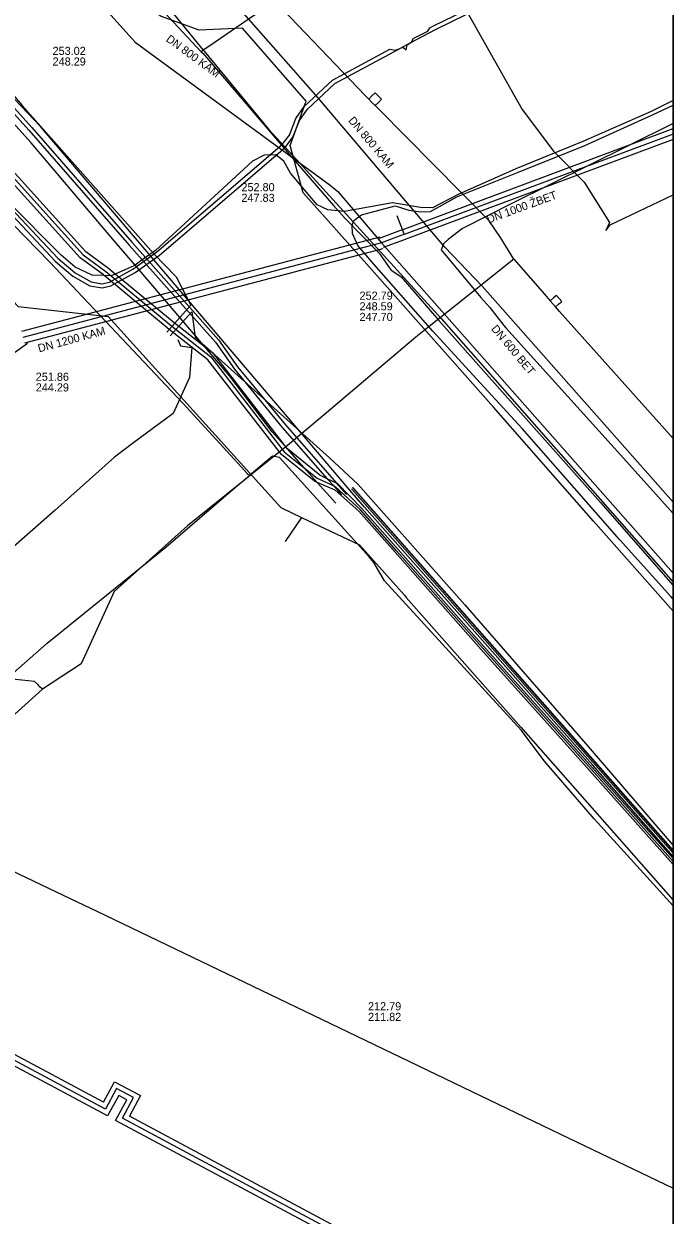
# Model space of a CAD drawing. Extents: x -598233 to -596890, y -1157848 to -1156431.
# Drawn here: x -596954.5 to -596890.5, y -1157685.2 to -1157567.6 of the extents above; entities that cross this region are included whole.
import ezdxf

# ---------------------------------------------------------------- set-up
doc = ezdxf.new("R2010")
doc.units = 0
for name, color, linetype in [('Vrstva 10', 7, 'Continuous'), ('Vrstva 12', 7, 'Continuous'), ('Vrstva 13', 7, 'Continuous'), ('Vrstva 19', 7, 'Continuous'), ('Vrstva 25', 7, 'Continuous'), ('Vrstva 26', 7, 'Continuous'), ('Vrstva 42', 7, 'Continuous'), ('Vrstva 44', 7, 'Continuous'), ('Vrstva 5', 7, 'Continuous'), ('Vrstva 55', 7, 'Continuous'), ('Vrstva 58', 7, 'Continuous'), ('Vrstva 60', 7, 'Continuous'), ('Vrstva 8', 7, 'Continuous'), ('Vrstva 9', 7, 'Continuous'), ('zajmove_uzemi', 7, 'Continuous')]:
    doc.layers.add(name, color=color, linetype=linetype)

msp = doc.modelspace()

# ---------------------------------------------------------------- linework, layer by layer
at = {"layer": 'Vrstva 10'}
for p, q in [((-596919.4, -1157588.66), (-596954.76, -1157597.98)), ((-596919.1, -1157589.82), (-596954.45, -1157599.14))]:
    msp.add_line(p, q, dxfattribs=at)
for points in [[(-596919.43, -1157588.77), (-596917.41, -1157588.01), (-596917.18, -1157587.93), (-596890.46, -1157577.95)], [(-596890.46, -1157579.02), (-596916.83, -1157588.87), (-596917.06, -1157588.95), (-596919.08, -1157589.7)], [(-596954.17, -1157599.17), (-596956.84, -1157601.09), (-596964.86, -1157604.79)]]:
    msp.add_lwpolyline(points, dxfattribs=at)
at = {"layer": 'Vrstva 12'}
for points in [[(-597004.51, -1157494.61), (-596998.59, -1157501.5), (-596997.43, -1157504.34), (-596996.05, -1157504.99), (-596988.03, -1157513.52), (-596962.05, -1157542.76), (-596956.17, -1157549.13), (-596955.06, -1157550.96), (-596953.42, -1157552.17), (-596940.63, -1157566.49), (-596937.01, -1157570.36)], [(-596908.75, -1157552.03), (-596914.18, -1157554.68), (-596933.54, -1157567.97), (-596936.17, -1157569.79), (-596936.81, -1157570.22)], [(-596940.36, -1157565.89), (-596936.81, -1157570.22)], [(-596936.81, -1157570.22), (-596937.01, -1157570.36)], [(-596937.01, -1157570.36), (-596936.87, -1157570.51), (-596927.74, -1157581.15), (-596923.96, -1157585.55)], [(-596936.81, -1157570.22), (-596936.74, -1157570.3), (-596930.39, -1157578.02), (-596927.6, -1157581.02), (-596924.03, -1157584.95)], [(-596890.46, -1157577.45), (-596894.96, -1157579.7), (-596906.38, -1157585.36), (-596911.24, -1157587.82), (-596912.65, -1157588.9)], [(-596961.18, -1157581.96), (-596959.24, -1157583.65), (-596951.95, -1157591.14), (-596938.83, -1157605.06), (-596933.05, -1157611.38)], [(-596924.03, -1157584.95), (-596921.34, -1157587.91)], [(-596923.96, -1157585.55), (-596922.82, -1157586.82)], [(-596922.82, -1157586.82), (-596919.47, -1157590.26), (-596918.3, -1157591.89), (-596917.28, -1157592.59), (-596913.58, -1157596.9), (-596897.63, -1157614.84), (-596890.46, -1157623.06)], [(-596921.34, -1157587.91), (-596913.36, -1157596.71), (-596890.46, -1157622.73)], [(-596912.65, -1157588.9), (-596913.11, -1157589.34), (-596913.34, -1157589.93), (-596909.44, -1157594.61), (-596908.55, -1157595.62), (-596907.18, -1157597.38), (-596906.96, -1157597.62)], [(-596906.96, -1157597.62), (-596895.65, -1157610.14), (-596890.46, -1157615.93)], [(-596890.46, -1157654.67), (-596898.27, -1157646.07), (-596903.2, -1157640.35), (-596905.41, -1157637.37), (-596918.95, -1157622.6), (-596919.99, -1157620.78), (-596920.44, -1157620.21), (-596929.3, -1157610.4), (-596929.99, -1157610.28), (-596932.26, -1157612.19)], [(-596933.05, -1157611.38), (-596932.49, -1157611.99), (-596932.26, -1157612.19)], [(-597014.95, -1157686.34), (-597013.23, -1157684.78), (-597010.06, -1157682.57), (-597007.42, -1157680.48), (-596999.58, -1157672.12), (-596995.14, -1157667.89), (-596981.85, -1157656.72), (-596979.91, -1157654.73), (-596976.27, -1157649.83), (-596971.68, -1157645.86), (-596965.97, -1157640.84), (-596952.21, -1157628.73), (-596940.5, -1157619.26), (-596933.64, -1157613.35), (-596932.26, -1157612.19)]]:
    msp.add_lwpolyline(points, dxfattribs=at)
at = {"layer": 'Vrstva 13'}
msp.add_line((-596927.11, -1157616.32), (-596928.74, -1157618.69), dxfattribs=at)
for points in [[(-596972.84, -1157575.03), (-596964.37, -1157585.79), (-596963.92, -1157586.27), (-596955.6, -1157594.95), (-596955.08, -1157595.5), (-596946.2, -1157596.49), (-596936.56, -1157607.15), (-596931.32, -1157612.96), (-596929.16, -1157615.35), (-596927.11, -1157616.32), (-596921.4, -1157619.04), (-596916.98, -1157624)], [(-596916.98, -1157624), (-596916.79, -1157624.23), (-596905.5, -1157637.03), (-596890.46, -1157654.09)]]:
    msp.add_lwpolyline(points, dxfattribs=at)
at = {"layer": 'Vrstva 19'}
for points in [[(-596920.49, -1157575.04), (-596920.84, -1157574.7), (-596932.64, -1157562.31)], [(-596920.18, -1157575.36), (-596920.49, -1157575.04), (-596920.18, -1157574.73)], [(-596919.86, -1157575.68), (-596919.54, -1157575.37), (-596919.22, -1157575.05), (-596919.85, -1157574.41), (-596920.18, -1157574.73)], [(-596919.86, -1157575.68), (-596920.18, -1157575.36)], [(-596906.17, -1157590.85), (-596907.5, -1157588.7), (-596908.6, -1157587.05), (-596919.54, -1157576.01), (-596919.86, -1157575.68)], [(-596906.17, -1157590.85), (-596911.85, -1157595.35)], [(-596906.17, -1157590.85), (-596903.4, -1157594.02), (-596902.59, -1157594.94), (-596902.33, -1157595.24)], [(-596902.33, -1157595.24), (-596902.07, -1157595.54), (-596901.76, -1157595.27), (-596901.45, -1157595.01), (-596901.98, -1157594.41), (-596902.28, -1157594.67), (-596902.59, -1157594.94)], [(-596911.85, -1157595.35), (-596914.36, -1157597.35), (-596915.85, -1157598.53), (-596925.09, -1157606.35), (-596928.51, -1157609.24), (-596938.36, -1157617.16), (-596945.59, -1157623.64), (-596948.86, -1157630.76), (-596952.68, -1157633.28)], [(-596890.46, -1157608.53), (-596901.66, -1157596), (-596902.07, -1157595.54)], [(-596953.15, -1157632.81), (-596953.45, -1157632.51), (-596956.6, -1157632.2), (-596957.02, -1157631.64), (-596964.22, -1157623.24), (-596965.08, -1157622.33), (-596972.86, -1157620.21), (-596973.81, -1157619.16), (-596985.37, -1157605.64), (-596986.1, -1157604.86), (-596988.52, -1157604.8)], [(-596952.68, -1157633.28), (-596952.89, -1157633.08), (-596953.15, -1157632.81)], [(-596952.68, -1157633.28), (-596971.44, -1157650.21), (-596981.79, -1157656.71), (-597002.57, -1157676.74), (-597002.84, -1157676.87), (-597001.55, -1157678.38), (-597001.29, -1157678.68)]]:
    msp.add_lwpolyline(points, dxfattribs=at)
at = {"layer": 'Vrstva 25'}
msp.add_line((-596902.32, -1157698.35), (-596944.78, -1157675.62), dxfattribs=at)
for points in [[(-596946.45, -1157674.72), (-596973.84, -1157660.06), (-596969.13, -1157651.32), (-596978.47, -1157646.29), (-597001.52, -1157643.75)], [(-596944.78, -1157675.62), (-596943.69, -1157673.59), (-596945.37, -1157672.7), (-596946.45, -1157674.72)]]:
    msp.add_lwpolyline(points, dxfattribs=at)
at = {"layer": 'Vrstva 26'}
for p, q in [((-596903.17, -1157698.46), (-596945.46, -1157675.83)), ((-596901.46, -1157698.24), (-596944.1, -1157675.42))]:
    msp.add_line(p, q, dxfattribs=at)
for points in [[(-596946.66, -1157674.05), (-596973.16, -1157659.86), (-596968.46, -1157651.11), (-596978.32, -1157645.81), (-597000.9, -1157643.31)], [(-596946.25, -1157675.4), (-596974.52, -1157660.27), (-596969.81, -1157651.52), (-596978.62, -1157646.78), (-597002.14, -1157644.18)], [(-596946.66, -1157674.05), (-596945.57, -1157672.02), (-596943.02, -1157673.39), (-596944.1, -1157675.42)], [(-596945.46, -1157675.83), (-596944.37, -1157673.8), (-596945.16, -1157673.37), (-596946.25, -1157675.4)]]:
    msp.add_lwpolyline(points, dxfattribs=at)
at = {"layer": 'Vrstva 42'}
for points in [[(-596916.12, -1157569.07), (-596914.66, -1157568.32), (-596914.46, -1157568.01), (-596914.1, -1157567.82), (-596904.93, -1157563.32), (-596900.35, -1157561.24), (-596896.86, -1157559.72), (-596890.46, -1157556.55)], [(-596956.56, -1157585.55), (-596951.43, -1157591.02), (-596949.69, -1157592.51), (-596948.01, -1157593.46), (-596946.8, -1157593.68), (-596945.92, -1157593.48), (-596943.55, -1157592.15), (-596941.14, -1157590.44), (-596928.74, -1157579.81), (-596927.97, -1157578.79), (-596927.32, -1157577.15), (-596926.55, -1157576.03), (-596923.84, -1157573.5), (-596918.03, -1157570.37), (-596917.41, -1157570.03), (-596916.33, -1157569.46), (-596913.92, -1157568.18), (-596904.76, -1157563.68)], [(-596916.81, -1157570.17), (-596916.69, -1157569.7), (-596916.33, -1157569.46), (-596916.24, -1157569.4), (-596916.12, -1157569.07)], [(-596956.28, -1157585.27), (-596951.15, -1157590.73), (-596949.46, -1157592.18), (-596947.87, -1157593.08), (-596946.81, -1157593.27), (-596946.06, -1157593.11), (-596943.76, -1157591.81), (-596941.39, -1157590.13), (-596929.03, -1157579.53), (-596928.32, -1157578.59), (-596927.67, -1157576.96), (-596926.86, -1157575.77), (-596924.08, -1157573.17), (-596918.42, -1157570.12), (-596917.84, -1157570.22), (-596917.41, -1157570.03), (-596917.12, -1157569.91), (-596916.81, -1157570.17)]]:
    msp.add_lwpolyline(points, dxfattribs=at)
at = {"layer": 'Vrstva 44'}
for points in [[(-597048.23, -1157471.62), (-597026.27, -1157496.48), (-597014.81, -1157509.39), (-596995.84, -1157530.92), (-596988.54, -1157539.16), (-596975.2, -1157554.18), (-596966.58, -1157564.14), (-596959.76, -1157571.73), (-596958.88, -1157572.71), (-596954.04, -1157578.1), (-596944.14, -1157589.44), (-596942.84, -1157590.91), (-596935.61, -1157599.04), (-596933.75, -1157601.71), (-596929.02, -1157607.44), (-596924.58, -1157612.51), (-596923.95, -1157613.21), (-596923.17, -1157614.11)], [(-597047.93, -1157471.36), (-597025.97, -1157496.22), (-597014.51, -1157509.12), (-596995.54, -1157530.65), (-596988.24, -1157538.89), (-596974.9, -1157553.91), (-596966.28, -1157563.87), (-596959.44, -1157571.49), (-596953.74, -1157577.83), (-596943.84, -1157589.18), (-596942.51, -1157590.67), (-596935.3, -1157598.79), (-596933.43, -1157601.47), (-596928.72, -1157607.18), (-596923.66, -1157612.95), (-596922.68, -1157614.06)], [(-596923.73, -1157614.93), (-596925.57, -1157612.88), (-596926.87, -1157611.42), (-596928.52, -1157609.57), (-596928.55, -1157609.53), (-596930.03, -1157607.89), (-596934.18, -1157602.39), (-596936.61, -1157599.54), (-596943.55, -1157591.43), (-596945.57, -1157589.06), (-596953.8, -1157579.35), (-596958.65, -1157573.99), (-596959.16, -1157573.43), (-596959.66, -1157572.87), (-596960.73, -1157571.69), (-596968.49, -1157563.13), (-596979.1, -1157551.08), (-596998.05, -1157529.68), (-597003.35, -1157523.66), (-597017.46, -1157507.77), (-597024.52, -1157499.73), (-597039.31, -1157483.02)], [(-596923.81, -1157613.63), (-596925.57, -1157612.88), (-596925.84, -1157612.76), (-596929.1, -1157610.13), (-596936.35, -1157600.76), (-596940.17, -1157597.78), (-596946.58, -1157592.46), (-596946.66, -1157592.39), (-596948.95, -1157590.69), (-596957.53, -1157581.22), (-596959.2, -1157578.28), (-596959.42, -1157574.21), (-596959.66, -1157572.87), (-596959.72, -1157572.54), (-596960.92, -1157570.64), (-596965, -1157566.02), (-596976.31, -1157553.17), (-596988.53, -1157539.3), (-596999.54, -1157527.05), (-597012.19, -1157512.7), (-597023.06, -1157500.47), (-597035.38, -1157486.5)], [(-597034.6, -1157486.78), (-597022.76, -1157500.21), (-597011.64, -1157512.71), (-596999.13, -1157526.91), (-596988.12, -1157539.15), (-596976.01, -1157552.9), (-596964.2, -1157566.33), (-596960.6, -1157570.4), (-596959.76, -1157571.73), (-596959.34, -1157572.39), (-596959.16, -1157573.43), (-596959.03, -1157574.14), (-596958.86, -1157578.08), (-596957.2, -1157580.98), (-596948.68, -1157590.4), (-596946.42, -1157592.07), (-596945.91, -1157592.49), (-596939.93, -1157597.46), (-596936.07, -1157600.47), (-596928.82, -1157609.85), (-596926.87, -1157611.42), (-596925.58, -1157612.45), (-596923.95, -1157613.21), (-596923.77, -1157613.3)], [(-596923.59, -1157612.98), (-596923.66, -1157612.95), (-596924.58, -1157612.51), (-596925.33, -1157612.15), (-596928.52, -1157609.57), (-596928.53, -1157609.56), (-596928.55, -1157609.53), (-596935.78, -1157600.19), (-596936.61, -1157599.54), (-596939.7, -1157597.13), (-596945.5, -1157592.32), (-596946.18, -1157591.75), (-596948.41, -1157590.1), (-596956.87, -1157580.75), (-596958.51, -1157577.88), (-596958.64, -1157574.07), (-596958.65, -1157573.99), (-596958.88, -1157572.71), (-596958.96, -1157572.25), (-596959.44, -1157571.49), (-596960.28, -1157570.16), (-596963.64, -1157566.36)], [(-596890.46, -1157575.18), (-596892.64, -1157576.26), (-596899.36, -1157579.23), (-596905.97, -1157581.92), (-596911.66, -1157584.45), (-596914.21, -1157585.77), (-596915.39, -1157585.74), (-596918.14, -1157585.28), (-596922.9, -1157586.14), (-596924.52, -1157585.97), (-596925.59, -1157585.47), (-596928.21, -1157582.34), (-596928.88, -1157581.17), (-596929.65, -1157580.53), (-596930.8, -1157580.56), (-596931.97, -1157581.17), (-596941.54, -1157589.97), (-596942.51, -1157590.67), (-596942.84, -1157590.91), (-596943.55, -1157591.43), (-596943.66, -1157591.5), (-596945.5, -1157592.32), (-596945.9, -1157592.49), (-596945.91, -1157592.49), (-596946.58, -1157592.46), (-596947.77, -1157592.41), (-596949.44, -1157591.64), (-596950.84, -1157590.44), (-596956.14, -1157585.1)], [(-596890.46, -1157624.39), (-596890.68, -1157624.14), (-596895.76, -1157618.49), (-596900.21, -1157613.44), (-596905.35, -1157607.55), (-596909.87, -1157602.65), (-596914.16, -1157597.95), (-596920, -1157591.33), (-596921.57, -1157589.5), (-596922.08, -1157588.3), (-596922.14, -1157587.47), (-596921.97, -1157587.02), (-596921.22, -1157586.46), (-596917.89, -1157585.56), (-596916.53, -1157586.01), (-596915.37, -1157586.15), (-596914.39, -1157586.13), (-596911.73, -1157584.66), (-596905.81, -1157582.27), (-596899.18, -1157579.61), (-596892.51, -1157576.58), (-596890.46, -1157575.64)], [(-596890.46, -1157650.59), (-596899.23, -1157640.71), (-596909.43, -1157629.34), (-596917.9, -1157619.74), (-596921.46, -1157615.71), (-596923.81, -1157613.63)], [(-596890.46, -1157650.3), (-596899.08, -1157640.58), (-596909.28, -1157629.21), (-596917.75, -1157619.61), (-596921.32, -1157615.57), (-596923.77, -1157613.3)], [(-596890.46, -1157650), (-596898.93, -1157640.45), (-596909.13, -1157629.08), (-596917.6, -1157619.48), (-596921.18, -1157615.43), (-596923.59, -1157612.98)]]:
    msp.add_lwpolyline(points, dxfattribs=at)
at = {"layer": 'Vrstva 5'}
for points in [[(-596976.12, -1157641.38), (-596973.57, -1157642.6), (-596961.74, -1157648.31), (-596949.88, -1157653.98), (-596947.33, -1157655.2), (-596939.58, -1157658.92), (-596922.56, -1157667.1)], [(-596922.56, -1157667.1), (-596900.74, -1157677.58), (-596890.46, -1157682.51)]]:
    msp.add_lwpolyline(points, dxfattribs=at)
at = {"layer": 'Vrstva 55'}
for points in [[(-596890.46, -1157625.57), (-596898.32, -1157616.7), (-596908.17, -1157605.45), (-596920.68, -1157591.34), (-596926.96, -1157584.28), (-596928.23, -1157579.62), (-596926.66, -1157575.25), (-596932.96, -1157568.03), (-596937.23, -1157568.24), (-596941.03, -1157566.85), (-596944.32, -1157564.19), (-596952.36, -1157555.39), (-596963.09, -1157543.7), (-596971.52, -1157534.16), (-596988.75, -1157514.15), (-596997.31, -1157504.51), (-597010.15, -1157490.51), (-597019.09, -1157480.36)], [(-597033.04, -1157487.14), (-597023, -1157498.31), (-597010.98, -1157511.9), (-596999.3, -1157525.02), (-596986.71, -1157538.57), (-596986.49, -1157539.55), (-596974.01, -1157553.37), (-596963.33, -1157565.46), (-596954.68, -1157575.66), (-596941.7, -1157590.32), (-596939.49, -1157592.59), (-596938.04, -1157595.39), (-596940.41, -1157598.04)], [(-596890.46, -1157545.84), (-596892.73, -1157546.89), (-596892.78, -1157546.77), (-596892.88, -1157546.97), (-596905.43, -1157553.26), (-596913.13, -1157556.83), (-596913.19, -1157556.71), (-596913.21, -1157556.87), (-596914.66, -1157557.68), (-596914.84, -1157558.27), (-596914.24, -1157559.5), (-596910.8, -1157566.4), (-596905.37, -1157576.08), (-596902.26, -1157580.17), (-596899.23, -1157583.24), (-596896.74, -1157587.21), (-596897.12, -1157588), (-596896.69, -1157587.46), (-596890.46, -1157584.5)], [(-596940.08, -1157598.42), (-596937.95, -1157596.04), (-596937.61, -1157598.54), (-596924.37, -1157610.45), (-596921.57, -1157613.04), (-596911.02, -1157624.94), (-596898.86, -1157638.93), (-596890.46, -1157648.71)], [(-596939.31, -1157598.75), (-596939.07, -1157599.4), (-596937.95, -1157599.56), (-596938.19, -1157602.53), (-596939.79, -1157606.06), (-596943.8, -1157609.03), (-596945.57, -1157610.39), (-596951.42, -1157615.61), (-596965.46, -1157627.96), (-596969.31, -1157631.16), (-596978.29, -1157638.7), (-596987.91, -1157646.32), (-596996.9, -1157653.86), (-597001.31, -1157657.39), (-597009.89, -1157665.09), (-597021.36, -1157675.11), (-597023.6, -1157677.44), (-597028.01, -1157680.65), (-597031.62, -1157684.42), (-597035.63, -1157691.87), (-597040.53, -1157701.26), (-597043.01, -1157706.71), (-597050.47, -1157721.63), (-597053.67, -1157726.84)]]:
    msp.add_lwpolyline(points, dxfattribs=at)
at = {"layer": 'Vrstva 58'}
for points in [[(-596922.36, -1157613.63), (-596952.88, -1157577.73), (-597153.35, -1157366.73), (-597150.38, -1157360.9), (-597143.15, -1157348.79), (-597141.76, -1157340.35), (-597141.76, -1157332.41), (-597142.33, -1157328.4), (-597136.65, -1157325.05), (-597127.33, -1157309.4), (-597155.19, -1157243.69), (-597168.69, -1157197.35), (-597171.83, -1157165.56), (-597168.69, -1157142.5), (-597162.65, -1157120.78), (-597150.78, -1157088.76), (-597134.89, -1157067.04), (-597115.64, -1157042.19), (-597035.06, -1156963.83)], [(-596890.46, -1157614.82), (-596909.26, -1157593.53), (-596912.98, -1157589.66), (-596925.72, -1157574.65), (-596933.08, -1157566.28), (-596951.7, -1157545.54), (-596968.04, -1157527.74), (-596993.62, -1157498.87), (-597020.42, -1157467.47), (-597038.85, -1157444.76), (-597043.88, -1157438.06), (-597052.55, -1157425.19), (-597063.82, -1157404.77), (-597067.27, -1157397.18)], [(-596890.46, -1157649.78), (-596898.43, -1157640.75), (-596920.9, -1157615.33), (-596922.36, -1157613.63)], [(-596890.46, -1157649.47), (-596922.14, -1157613.58), (-596922.2, -1157613.51)], [(-596890.46, -1157649.24), (-596921.99, -1157613.45), (-596922.13, -1157613.39)], [(-596890.46, -1157649.16), (-596921.98, -1157613.45), (-596922.03, -1157613.38)]]:
    msp.add_lwpolyline(points, dxfattribs=at)
at = {"layer": 'Vrstva 60'}
msp.add_lwpolyline([(-596890.46, -1157848.46), (-596890.46, -1156430.86)], dxfattribs=at)
at = {"layer": 'Vrstva 9'}
for p, q in [((-596943.52, -1157569.41), (-596924.29, -1157583.52)), ((-596917.71, -1157586.52), (-596917.01, -1157588.4)), ((-596919.25, -1157589.24), (-596954.61, -1157598.56)), ((-596890.46, -1157621.82), (-596919.25, -1157589.24))]:
    msp.add_line(p, q, dxfattribs=at)
for points in [[(-596973.63, -1157536.03), (-596959.68, -1157551.49), (-596959.5, -1157551.69), (-596959.36, -1157551.85), (-596959.26, -1157551.95), (-596959.11, -1157552.12), (-596943.52, -1157569.41)], [(-596890.46, -1157578.49), (-596917.01, -1157588.4), (-596917.23, -1157588.48), (-596919.25, -1157589.24)], [(-596924.29, -1157583.52), (-596923.53, -1157584.15), (-596919.25, -1157589.24)]]:
    msp.add_lwpolyline(points, dxfattribs=at)
at = {"layer": 'zajmove_uzemi'}
msp.add_lwpolyline([(-598232.89, -1156430.86), (-596890.46, -1156430.86), (-596890.46, -1157848.46), (-598232.89, -1157848.46)], close=True, dxfattribs=at)

# ---------------------------------------------------------------- texts
at = {"layer": 'Vrstva 12'}
for s, rotation, p in [('DN 800 KAM', 323.7212, (-596940.56, -1157569.27)), ('DN 800 KAM', 310.0848, (-596922.56, -1157577.18)), ('DN 1000 ŽBET', 20.1108, (-596908.67, -1157587.32)), ('DN 1200 KAM', 15.1261, (-596953.01, -1157600.04)), ('DN 600 BET', 309.9702, (-596908.47, -1157597.74))]:
    msp.add_text(s, height=0.8, rotation=rotation, dxfattribs=at).set_placement(p)
for s, p in [('253.02', (-596951.68, -1157570.68)), ('248.29', (-596951.68, -1157571.73)), ('252.80', (-596933.05, -1157584.13)), ('247.83', (-596933.05, -1157585.18)), ('252.79', (-596921.4, -1157594.84)), ('248.59', (-596921.4, -1157595.89)), ('247.70', (-596921.4, -1157596.94)), ('251.86', (-596953.34, -1157602.84)), ('244.29', (-596953.34, -1157603.89))]:
    msp.add_text(s, height=0.8, dxfattribs=at).set_placement(p)
at = {"layer": 'Vrstva 8'}
for s, p in [('212.79', (-596920.56, -1157664.97)), ('211.82', (-596920.56, -1157666.02))]:
    msp.add_text(s, height=0.8, dxfattribs=at).set_placement(p)

doc.saveas('drawing.dxf')
